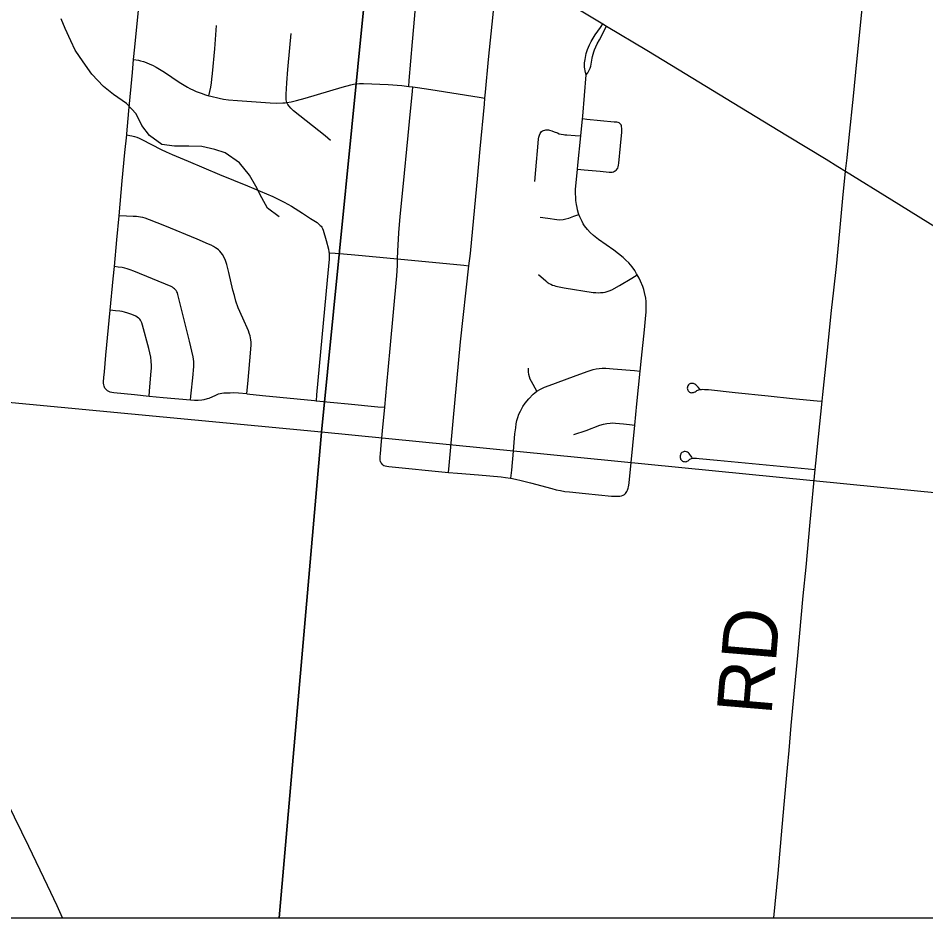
# Model space of a CAD drawing. Extents: x 0 to 1067, y 0 to 440.
# Drawn here: x 803.284 to 804.224, y 350.802 to 351.734 of the extents above; entities that cross this region are included whole.
import ezdxf

# ---------------------------------------------------------------- set-up
doc = ezdxf.new("R2010")
doc.units = 0
for name, color, linetype in [('GM_X_City_Street', 7, 'Continuous'), ('GM_X_County_Road', 7, 'Continuous'), ('GM_X_Minor_River', 7, 'Continuous'), ('GM_X_Section', 7, 'Continuous'), ('GM_X_State_Route', 7, 'Continuous'), ('GM_X_Township_Road', 7, 'Continuous'), ('GM_X_Township_Road_Text', 7, 'Continuous'), ('GM_X_US_Shield', 7, 'Continuous')]:
    doc.layers.add(name, color=color, linetype=linetype)

msp = doc.modelspace()

# ---------------------------------------------------------------- linework, layer by layer
at = {"layer": 'GM_X_City_Street'}
for points in [[(803.6888, 351.66326), (803.68919, 351.66916), (803.69256, 351.70933), (803.69485, 351.73665), (803.69678, 351.75991), (803.69724, 351.76508), (803.69757, 351.76815), (803.69815, 351.77115), (803.69885, 351.77351), (803.70097, 351.78), (803.70787, 351.79862), (803.71115, 351.80789), (803.71514, 351.81869), (803.71687, 351.82306), (803.71938, 351.82859), (803.72088, 351.8319)], [(803.72973, 351.26351), (803.73039, 351.27075), (803.73455, 351.31654), (803.74228, 351.39882), (803.75104, 351.47739), (803.75246, 351.49022), (803.75502, 351.51619), (803.75975, 351.56755), (803.76258, 351.59848), (803.76699, 351.64484), (803.76757, 351.65116), (803.76812, 351.65721), (803.77127, 351.69122), (803.77594, 351.73756), (803.77936, 351.7712), (803.77996, 351.77514), (803.78065, 351.7782), (803.78144, 351.78067), (803.78262, 351.78333), (803.78658, 351.79044)], [(803.3888, 351.5291), (803.39195, 351.56529), (803.39478, 351.59488), (803.39658, 351.61301), (803.39667, 351.61395), (803.39888, 351.63801), (803.40246, 351.67754), (803.4037, 351.69113), (803.40487, 351.70396), (803.41084, 351.76317)], [(803.48182, 351.6536), (803.48282, 351.65782), (803.48373, 351.66239), (803.48445, 351.66695), (803.4849, 351.67086), (803.48552, 351.67667), (803.48773, 351.70206), (803.48964, 351.72633)], [(803.87254, 351.67511), (803.87177, 351.67749), (803.87129, 351.67951), (803.87087, 351.68151), (803.8706, 351.68326), (803.87054, 351.68506), (803.87077, 351.68776), (803.87119, 351.6912), (803.87241, 351.69722), (803.87298, 351.69929), (803.87378, 351.7014), (803.87473, 351.70383), (803.87579, 351.70621), (803.87753, 351.7096), (803.88176, 351.71669), (803.88718, 351.72423), (803.88979, 351.72786)], [(803.87254, 351.67511), (803.87405, 351.67723), (803.87494, 351.67877), (803.87595, 351.68056), (803.87658, 351.68204), (803.87717, 351.68406), (803.87758, 351.68612), (803.87859, 351.69247), (803.87891, 351.69405), (803.87955, 351.69664), (803.88028, 351.69892), (803.88108, 351.70103), (803.8824, 351.70421), (803.88378, 351.70716), (803.8861, 351.71129), (803.88748, 351.71378), (803.88843, 351.71558), (803.89362, 351.72553)], [(803.56241, 351.64649), (803.56185, 351.64947), (803.56168, 351.6521), (803.5616, 351.65532), (803.56193, 351.66075), (803.5623, 351.66687), (803.56355, 351.6808), (803.56562, 351.70306), (803.56701, 351.7179)], [(803.4037, 351.69113), (803.40875, 351.69033), (803.41093, 351.68981), (803.41403, 351.68888), (803.41678, 351.68793), (803.42039, 351.68637), (803.42316, 351.68508), (803.42705, 351.68304), (803.4356, 351.67798), (803.45107, 351.66755), (803.45952, 351.66232), (803.46209, 351.66093), (803.46562, 351.65925), (803.46847, 351.65808), (803.47373, 351.65611), (803.4783, 351.65463), (803.48182, 351.6536), (803.48383, 351.65302), (803.49238, 351.65086), (803.49695, 351.65004), (803.50211, 351.64933), (803.51125, 351.64851), (803.54512, 351.64605), (803.55174, 351.64585), (803.55819, 351.64607), (803.56066, 351.6463), (803.56241, 351.64649), (803.56694, 351.64735), (803.57259, 351.6487), (803.58153, 351.6511), (803.61961, 351.66256), (803.62862, 351.66494), (803.63155, 351.6655), (803.63425, 351.66596), (803.63755, 351.66625), (803.64168, 351.66633), (803.66749, 351.6651), (803.68136, 351.66409), (803.6888, 351.66326), (803.69307, 351.66269), (803.69779, 351.66205), (803.71143, 351.6601), (803.76173, 351.65197), (803.76757, 351.65116)], [(803.91072, 351.2397), (803.91199, 351.24048), (803.91324, 351.24162), (803.91399, 351.24252), (803.91463, 351.24367), (803.91524, 351.24507), (803.91591, 351.24716), (803.91626, 351.24864), (803.91654, 351.25027), (803.91688, 351.25265), (803.92282, 351.31253), (803.92499, 351.33429), (803.92848, 351.36837), (803.92986, 351.3819), (803.93276, 351.41096), (803.93427, 351.42616), (803.93452, 351.4295), (803.9347, 351.43249), (803.9347, 351.43572), (803.93442, 351.44029), (803.93406, 351.44377), (803.93294, 351.44988), (803.93216, 351.45279), (803.93119, 351.45584), (803.92877, 351.46156), (803.92727, 351.46448), (803.92533, 351.46796), (803.92463, 351.46921), (803.92265, 351.47255), (803.91993, 351.47635), (803.91657, 351.48043), (803.91358, 351.48342), (803.91078, 351.48587), (803.90099, 351.49348), (803.88528, 351.50465), (803.88015, 351.50871), (803.8767, 351.51197), (803.8738, 351.51505), (803.87071, 351.51896), (803.86936, 351.52094), (803.8681, 351.52319), (803.86577, 351.52827), (803.86487, 351.53071), (803.86453, 351.53165), (803.86349, 351.53552), (803.86302, 351.53779), (803.86241, 351.54085), (803.86184, 351.54504), (803.86156, 351.54826), (803.8613, 351.5522), (803.86139, 351.55634), (803.86339, 351.57748), (803.86379, 351.5817), (803.86679, 351.61209), (803.86852, 351.62953), (803.86881, 351.63241), (803.87254, 351.67511)], [(803.66102, 351.27203), (803.66032, 351.27293), (803.65993, 351.27372), (803.65953, 351.2748), (803.65924, 351.27603), (803.6591, 351.27761), (803.65909, 351.27979), (803.65928, 351.28259), (803.6601, 351.29149), (803.66156, 351.30633), (803.6638, 351.33084), (803.66597, 351.35458), (803.66944, 351.39168), (803.67632, 351.46702), (803.67686, 351.47781), (803.67703, 351.48446), (803.67725, 351.49269), (803.67848, 351.51143), (803.67979, 351.52831), (803.68284, 351.55932), (803.688, 351.61247), (803.69024, 351.63407), (803.69259, 351.65783), (803.69307, 351.66269)], [(803.60759, 351.60733), (803.60215, 351.61188), (803.58231, 351.62761), (803.5694, 351.63802), (803.56651, 351.64065), (803.56473, 351.64268), (803.56346, 351.64447), (803.56241, 351.64649)], [(803.86339, 351.57748), (803.87027, 351.57686), (803.88698, 351.57535), (803.89626, 351.57442), (803.89789, 351.57439), (803.89936, 351.57448), (803.90062, 351.57483), (803.90173, 351.57533), (803.90256, 351.57578), (803.9033, 351.57633), (803.9039, 351.57686), (803.90455, 351.57768), (803.90503, 351.57855), (803.90554, 351.57998), (803.90598, 351.58162), (803.90624, 351.58364), (803.90789, 351.60159), (803.90927, 351.61583), (803.90935, 351.6194), (803.9093, 351.62009), (803.90914, 351.62125), (803.90892, 351.62225), (803.90849, 351.62333), (803.90793, 351.62424), (803.90736, 351.62493), (803.90654, 351.62545), (803.90559, 351.62575), (803.90403, 351.62606), (803.90148, 351.6263), (803.87305, 351.62909), (803.86852, 351.62953)], [(803.81939, 351.56457), (803.82035, 351.57674), (803.82264, 351.60451), (803.82316, 351.60901), (803.82355, 351.61074), (803.82415, 351.61282), (803.82476, 351.61438), (803.82532, 351.61541), (803.82628, 351.61645), (803.82714, 351.61706), (803.82826, 351.61758), (803.82948, 351.61788), (803.83073, 351.6181), (803.83203, 351.61823), (803.83333, 351.61814), (803.83454, 351.61788), (803.83678, 351.61715), (803.83934, 351.61619), (803.8426, 351.61498), (803.84457, 351.61424), (803.84657, 351.61372), (803.84886, 351.61329), (803.85046, 351.61308), (803.85229, 351.61292), (803.86085, 351.61243), (803.86679, 351.61209)], [(803.39658, 351.61301), (803.39969, 351.61247), (803.40197, 351.612), (803.40455, 351.61136), (803.40714, 351.61053), (803.40957, 351.60946), (803.41242, 351.60807), (803.43231, 351.59787), (803.43763, 351.59532), (803.44357, 351.59264), (803.46016, 351.58563), (803.4928, 351.57196), (803.52154, 351.56021), (803.5478, 351.54903), (803.554, 351.54614), (803.55953, 351.54338), (803.56711, 351.53915), (803.57861, 351.53177), (803.58705, 351.52653), (803.5938, 351.5221), (803.59493, 351.52123), (803.59598, 351.52034), (803.59706, 351.51922), (803.59785, 351.51834), (803.59857, 351.51726), (803.59928, 351.51596), (803.59989, 351.51446), (803.60321, 351.50378), (803.60549, 351.49475), (803.60599, 351.49195), (803.60611, 351.49085), (803.60627, 351.48922), (803.6063, 351.48669), (803.60628, 351.48426), (803.60433, 351.46262), (803.59324, 351.34394), (803.59265, 351.33772)], [(803.52102, 351.34476), (803.51239, 351.3454), (803.50705, 351.34568), (803.50391, 351.34565), (803.49974, 351.34565), (803.49719, 351.34548), (803.49512, 351.34524), (803.49323, 351.34483), (803.49141, 351.34433), (803.48845, 351.34317), (803.4816, 351.34012), (803.47987, 351.33954), (803.47641, 351.33864), (803.47435, 351.33823), (803.47064, 351.33798), (803.46666, 351.33793), (803.46259, 351.33829), (803.4345, 351.34078), (803.41977, 351.34219), (803.40484, 351.34362), (803.38322, 351.34574), (803.38104, 351.34613), (803.37958, 351.34657), (803.37802, 351.34719), (803.37681, 351.34794), (803.37573, 351.34879), (803.37498, 351.34958), (803.37412, 351.35067), (803.37365, 351.35167), (803.37321, 351.35282), (803.3729, 351.35403), (803.37271, 351.35571), (803.37268, 351.35712), (803.37298, 351.36157), (803.37351, 351.36764), (803.37515, 351.38495), (803.37957, 351.43144), (803.38266, 351.46404), (803.38385, 351.47669), (803.38646, 351.50421), (803.3888, 351.5291)], [(803.52102, 351.34476), (803.52234, 351.35909), (803.52495, 351.3869), (803.52546, 351.39558), (803.52546, 351.39815), (803.52518, 351.40079), (803.52484, 351.40285), (803.52438, 351.40479), (803.52346, 351.40766), (803.52257, 351.41008), (803.5167, 351.42308), (803.51203, 351.4339), (803.50958, 351.44091), (803.50812, 351.44654), (803.50667, 351.45233), (803.50228, 351.47044), (803.50022, 351.47885), (803.49888, 351.48297), (803.49746, 351.48611), (803.4958, 351.48915), (803.49454, 351.49092), (803.49311, 351.49252), (803.49156, 351.4939), (803.49019, 351.49505), (803.48859, 351.49619), (803.48652, 351.49745), (803.48401, 351.49877), (803.48131, 351.49997), (803.46947, 351.5049), (803.43625, 351.5187), (803.42014, 351.52515), (803.41562, 351.52678), (803.4134, 351.52736), (803.4108, 351.52784), (803.40687, 351.52832), (803.40336, 351.52852), (803.39632, 351.52871), (803.3888, 351.5291)], [(803.82475, 351.52792), (803.83258, 351.52659), (803.84197, 351.52532), (803.8451, 351.52517), (803.84845, 351.5254), (803.8512, 351.52592), (803.85455, 351.52689), (803.85963, 351.52877), (803.86487, 351.53071)], [(803.60611, 351.49085), (803.61246, 351.49045), (803.6174, 351.49014), (803.63661, 351.48843), (803.67314, 351.48481), (803.67703, 351.48446), (803.74564, 351.47791), (803.75104, 351.47739)], [(803.46259, 351.33829), (803.46305, 351.34238), (803.46338, 351.34547), (803.46503, 351.36153), (803.466, 351.37328), (803.46605, 351.37825), (803.4654, 351.38318), (803.46155, 351.39949), (803.44954, 351.44769), (803.44906, 351.44935), (803.44846, 351.45059), (803.44782, 351.45168), (803.44705, 351.45263), (803.4462, 351.45355), (803.44505, 351.4544), (803.4439, 351.45512), (803.44253, 351.45584), (803.4041, 351.47183), (803.40011, 351.47334), (803.39708, 351.4743), (803.39458, 351.47501), (803.39196, 351.47556), (803.38766, 351.47616), (803.38385, 351.47669)], [(803.82309, 351.46847), (803.83058, 351.46169), (803.83208, 351.46054), (803.83415, 351.45921), (803.83565, 351.45832), (803.83745, 351.45752), (803.83916, 351.45686), (803.84097, 351.45635), (803.8495, 351.45471), (803.87951, 351.44992), (803.88227, 351.44961), (803.88508, 351.44956), (803.88719, 351.44961), (803.89003, 351.44989), (803.89217, 351.45027), (803.89425, 351.45087), (803.89633, 351.45161), (803.89886, 351.45269), (803.90702, 351.45716), (803.91984, 351.46472), (803.92533, 351.46796)], [(803.41977, 351.34219), (803.42028, 351.34784), (803.42211, 351.36829), (803.42228, 351.37123), (803.42235, 351.37427), (803.42206, 351.37877), (803.42146, 351.38283), (803.4194, 351.3917), (803.41296, 351.41608), (803.41223, 351.41822), (803.41157, 351.41985), (803.41099, 351.42097), (803.41021, 351.42211), (803.40964, 351.42278), (803.40898, 351.42334), (803.40752, 351.42435), (803.40602, 351.42517), (803.40354, 351.42631), (803.40071, 351.42745), (803.39775, 351.42842), (803.39426, 351.42937), (803.39199, 351.42994), (803.3894, 351.43039), (803.38507, 351.43085), (803.37957, 351.43144)], [(803.79455, 351.25742), (803.79537, 351.26577), (803.79729, 351.28549), (803.79867, 351.3034), (803.79943, 351.30957), (803.80003, 351.31381), (803.80074, 351.31714), (803.80155, 351.32027), (803.80276, 351.3237), (803.80428, 351.32694), (803.8068, 351.33178), (803.80922, 351.33521), (803.81295, 351.33965), (803.8175, 351.3445), (803.81909, 351.34594), (803.82134, 351.34762), (803.82496, 351.34964), (803.82706, 351.35067), (803.82931, 351.35156), (803.83425, 351.35358), (803.85931, 351.36287), (803.8733, 351.36796), (803.87654, 351.36912), (803.87957, 351.36993), (803.8829, 351.37054), (803.88603, 351.37094), (803.88906, 351.37124), (803.89277, 351.37131), (803.90019, 351.37086), (803.92243, 351.3689), (803.92848, 351.36837)], [(803.82134, 351.34762), (803.81571, 351.3576), (803.81457, 351.35984), (803.81366, 351.36236), (803.81295, 351.36488), (803.81265, 351.36751), (803.81256, 351.37144)], [(803.52102, 351.34476), (803.53734, 351.34297), (803.5912, 351.33787), (803.59265, 351.33772), (803.611, 351.3359), (803.62585, 351.33447), (803.65682, 351.33152), (803.6638, 351.33084)], [(803.8596, 351.30256), (803.87252, 351.30699), (803.88647, 351.31225), (803.89041, 351.31349), (803.89387, 351.3142), (803.89734, 351.3146), (803.89993, 351.31475), (803.90293, 351.31458), (803.91096, 351.31381), (803.91713, 351.31314), (803.92282, 351.31253)], [(803.66102, 351.27203), (803.66195, 351.27135), (803.66299, 351.27075), (803.66417, 351.27031), (803.66585, 351.26991), (803.66794, 351.26958), (803.72973, 351.26351), (803.73906, 351.26259), (803.76075, 351.2609), (803.78426, 351.25878), (803.78894, 351.25826), (803.7939, 351.25755), (803.79455, 351.25742), (803.7993, 351.25649), (803.80523, 351.25499), (803.81461, 351.2526), (803.83675, 351.24667), (803.84144, 351.24542), (803.84577, 351.24454), (803.85029, 351.24383), (803.85516, 351.24321), (803.87187, 351.24153), (803.89846, 351.23892), (803.90206, 351.23871), (803.9059, 351.23868), (803.9074, 351.23881), (803.90898, 351.23909), (803.91072, 351.2397)]]:
    msp.add_lwpolyline(points, dxfattribs=at)
at = {"layer": 'GM_X_County_Road'}
msp.add_lwpolyline([(803.33028, 350.8021), (803.32468, 350.81437), (803.31451, 350.83567), (803.29509, 350.87598), (803.27322, 350.9213)], dxfattribs=at)
at = {"layer": 'GM_X_Minor_River'}
msp.add_lwpolyline([(803.55454, 351.52826), (803.5425, 351.53708), (803.53654, 351.54775), (803.53021, 351.55993), (803.52387, 351.57136), (803.51338, 351.58395), (803.49871, 351.59431), (803.48777, 351.59781), (803.47456, 351.60095), (803.46094, 351.60143), (803.44618, 351.60117), (803.43296, 351.60317), (803.42017, 351.61238), (803.41231, 351.62268), (803.40636, 351.63486), (803.39623, 351.64555), (803.38306, 351.65476), (803.37254, 351.66318), (803.36054, 351.67579), (803.35157, 351.68876), (803.34334, 351.70057), (803.33888, 351.71047), (803.33293, 351.72303), (803.32886, 351.7333)], dxfattribs=at)
at = {"layer": 'GM_X_Section'}
for points in [[(802.69313, 352.42359), (803.69832, 352.31199), (803.59844, 351.30514), (802.59985, 351.39962)], [(803.69832, 352.31199), (804.2114, 352.24697), (804.70936, 352.21205), (804.61325, 351.20476), (803.59844, 351.30514)]]:
    msp.add_lwpolyline(points, close=True, dxfattribs=at)
at = {"layer": 'GM_X_State_Route'}
for points in [[(803.81727, 351.77195), (803.88979, 351.72786), (803.89362, 351.72553), (803.93509, 351.7008)], [(803.93509, 351.7008), (803.96089, 351.68512), (804.03146, 351.64195), (804.08098, 351.61204), (804.12081, 351.58776), (804.13301, 351.58026), (804.14104, 351.57533)], [(804.14104, 351.57533), (804.18894, 351.54568), (804.27348, 351.49337), (804.30743, 351.47266), (804.32505, 351.46216), (804.38398, 351.42628), (804.43597, 351.39453), (804.47522, 351.37056), (804.51094, 351.34883), (804.52408, 351.34084), (804.58457, 351.30434), (804.60179, 351.29403), (804.63812, 351.272), (804.68499, 351.24388), (804.73871, 351.21108), (804.80654, 351.17195), (804.83363, 351.15677), (804.84013, 351.15323)]]:
    msp.add_lwpolyline(points, dxfattribs=at)
at = {"layer": 'GM_X_Township_Road'}
for points in [[(799.45716, 350.8021), (804.84013, 350.8021), (804.84013, 353.20497), (804.2178, 353.26891), (803.29273, 353.36362)], [(804.14104, 351.57533), (804.14261, 351.58934), (804.14473, 351.61036), (804.1492, 351.65299), (804.15284, 351.68882), (804.15792, 351.74013), (804.16517, 351.81244), (804.17658, 351.92364), (804.18248, 351.97986), (804.18759, 352.03177), (804.18793, 352.03545)], [(804.11685, 351.33711), (804.11757, 351.34404), (804.12208, 351.38666), (804.1266, 351.43115), (804.12882, 351.45215), (804.13153, 351.47684), (804.13504, 351.51334), (804.13826, 351.54735), (804.14104, 351.57533)], [(803.99002, 351.34975), (803.98843, 351.35165), (803.98676, 351.35337), (803.98587, 351.35415), (803.98501, 351.35478), (803.98422, 351.35523), (803.98339, 351.35549), (803.98244, 351.3556), (803.98161, 351.35561), (803.98059, 351.35548), (803.97974, 351.35518), (803.97907, 351.3548), (803.97824, 351.354), (803.97772, 351.35323), (803.97737, 351.35242), (803.97722, 351.3518), (803.97712, 351.35052), (803.97721, 351.34972), (803.97767, 351.34852), (803.97801, 351.34797), (803.97869, 351.34722), (803.97942, 351.3466), (803.98007, 351.34627), (803.98087, 351.34607), (803.98172, 351.34599), (803.98257, 351.34607), (803.98344, 351.34624), (803.98435, 351.34652), (803.98532, 351.34702), (803.98625, 351.3476), (803.98712, 351.34812), (803.98812, 351.34864), (803.98902, 351.34897), (803.98986, 351.34921), (803.99169, 351.34943), (803.99314, 351.34951), (803.99485, 351.34944), (803.99924, 351.34914), (804.0268, 351.34624), (804.0608, 351.34277), (804.08613, 351.34007), (804.11148, 351.33762), (804.11685, 351.33711)], [(804.1095, 351.26652), (804.11024, 351.27298), (804.11301, 351.30017), (804.11685, 351.33711)], [(803.98211, 351.2788), (803.98083, 351.28059), (803.97987, 351.28207), (803.97908, 351.28307), (803.97821, 351.28384), (803.97724, 351.2844), (803.97614, 351.28481), (803.97507, 351.28496), (803.97404, 351.28492), (803.97317, 351.28474), (803.97237, 351.28442), (803.97158, 351.28391), (803.97058, 351.28289), (803.97026, 351.28219), (803.97, 351.28152), (803.96983, 351.28071), (803.96974, 351.27986), (803.9698, 351.27882), (803.96995, 351.27797), (803.97021, 351.27724), (803.9707, 351.27638), (803.9714, 351.27567), (803.97214, 351.27524), (803.97285, 351.27485), (803.97385, 351.27461), (803.97506, 351.27448), (803.97593, 351.27457), (803.97655, 351.27472), (803.97713, 351.27501), (803.97792, 351.27549), (803.97911, 351.27649), (803.97989, 351.27704), (803.98076, 351.27766), (803.98152, 351.27797), (803.98247, 351.27824), (803.98367, 351.27835), (803.98475, 351.27835), (803.98661, 351.2782), (803.98947, 351.27792), (804.00791, 351.276), (804.1095, 351.26652)], [(804.08094, 350.95762), (804.08248, 350.97538), (804.08477, 351.00139), (804.08773, 351.03418), (804.09144, 351.07378), (804.09718, 351.13566), (804.10019, 351.16534), (804.10437, 351.21177), (804.1095, 351.26652)], [(804.06683, 350.8021), (804.07109, 350.84787), (804.07548, 350.89614), (804.07779, 350.9234), (804.0806, 350.95371), (804.08094, 350.95762)]]:
    msp.add_lwpolyline(points, dxfattribs=at)
at = {"layer": 'GM_X_US_Shield'}
for points in [[(802.54874, 350.8021), (803.55442, 350.8021), (803.59844, 351.30514), (802.59985, 351.39962)], [(803.55442, 350.8021), (804.57328, 350.8021), (804.61325, 351.20476), (803.59844, 351.30514)]]:
    msp.add_lwpolyline(points, close=True, dxfattribs=at)

# ---------------------------------------------------------------- texts
at = {"layer": 'GM_X_Township_Road_Text'}
msp.add_text('RD', height=0.056818, rotation=85.15986, dxfattribs=at).set_placement((804.06411, 351.01117))

doc.saveas('drawing.dxf')
